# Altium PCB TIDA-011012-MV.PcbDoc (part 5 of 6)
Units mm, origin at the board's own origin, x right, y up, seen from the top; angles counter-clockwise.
Board outline 360 x 280 mm, 4 copper layers (Top Layer, Layer 1, Layer 2, Bottom Layer), stack 2.066 mm thick; 566 components, 345 nets, 1738 pads, 2486 vias.
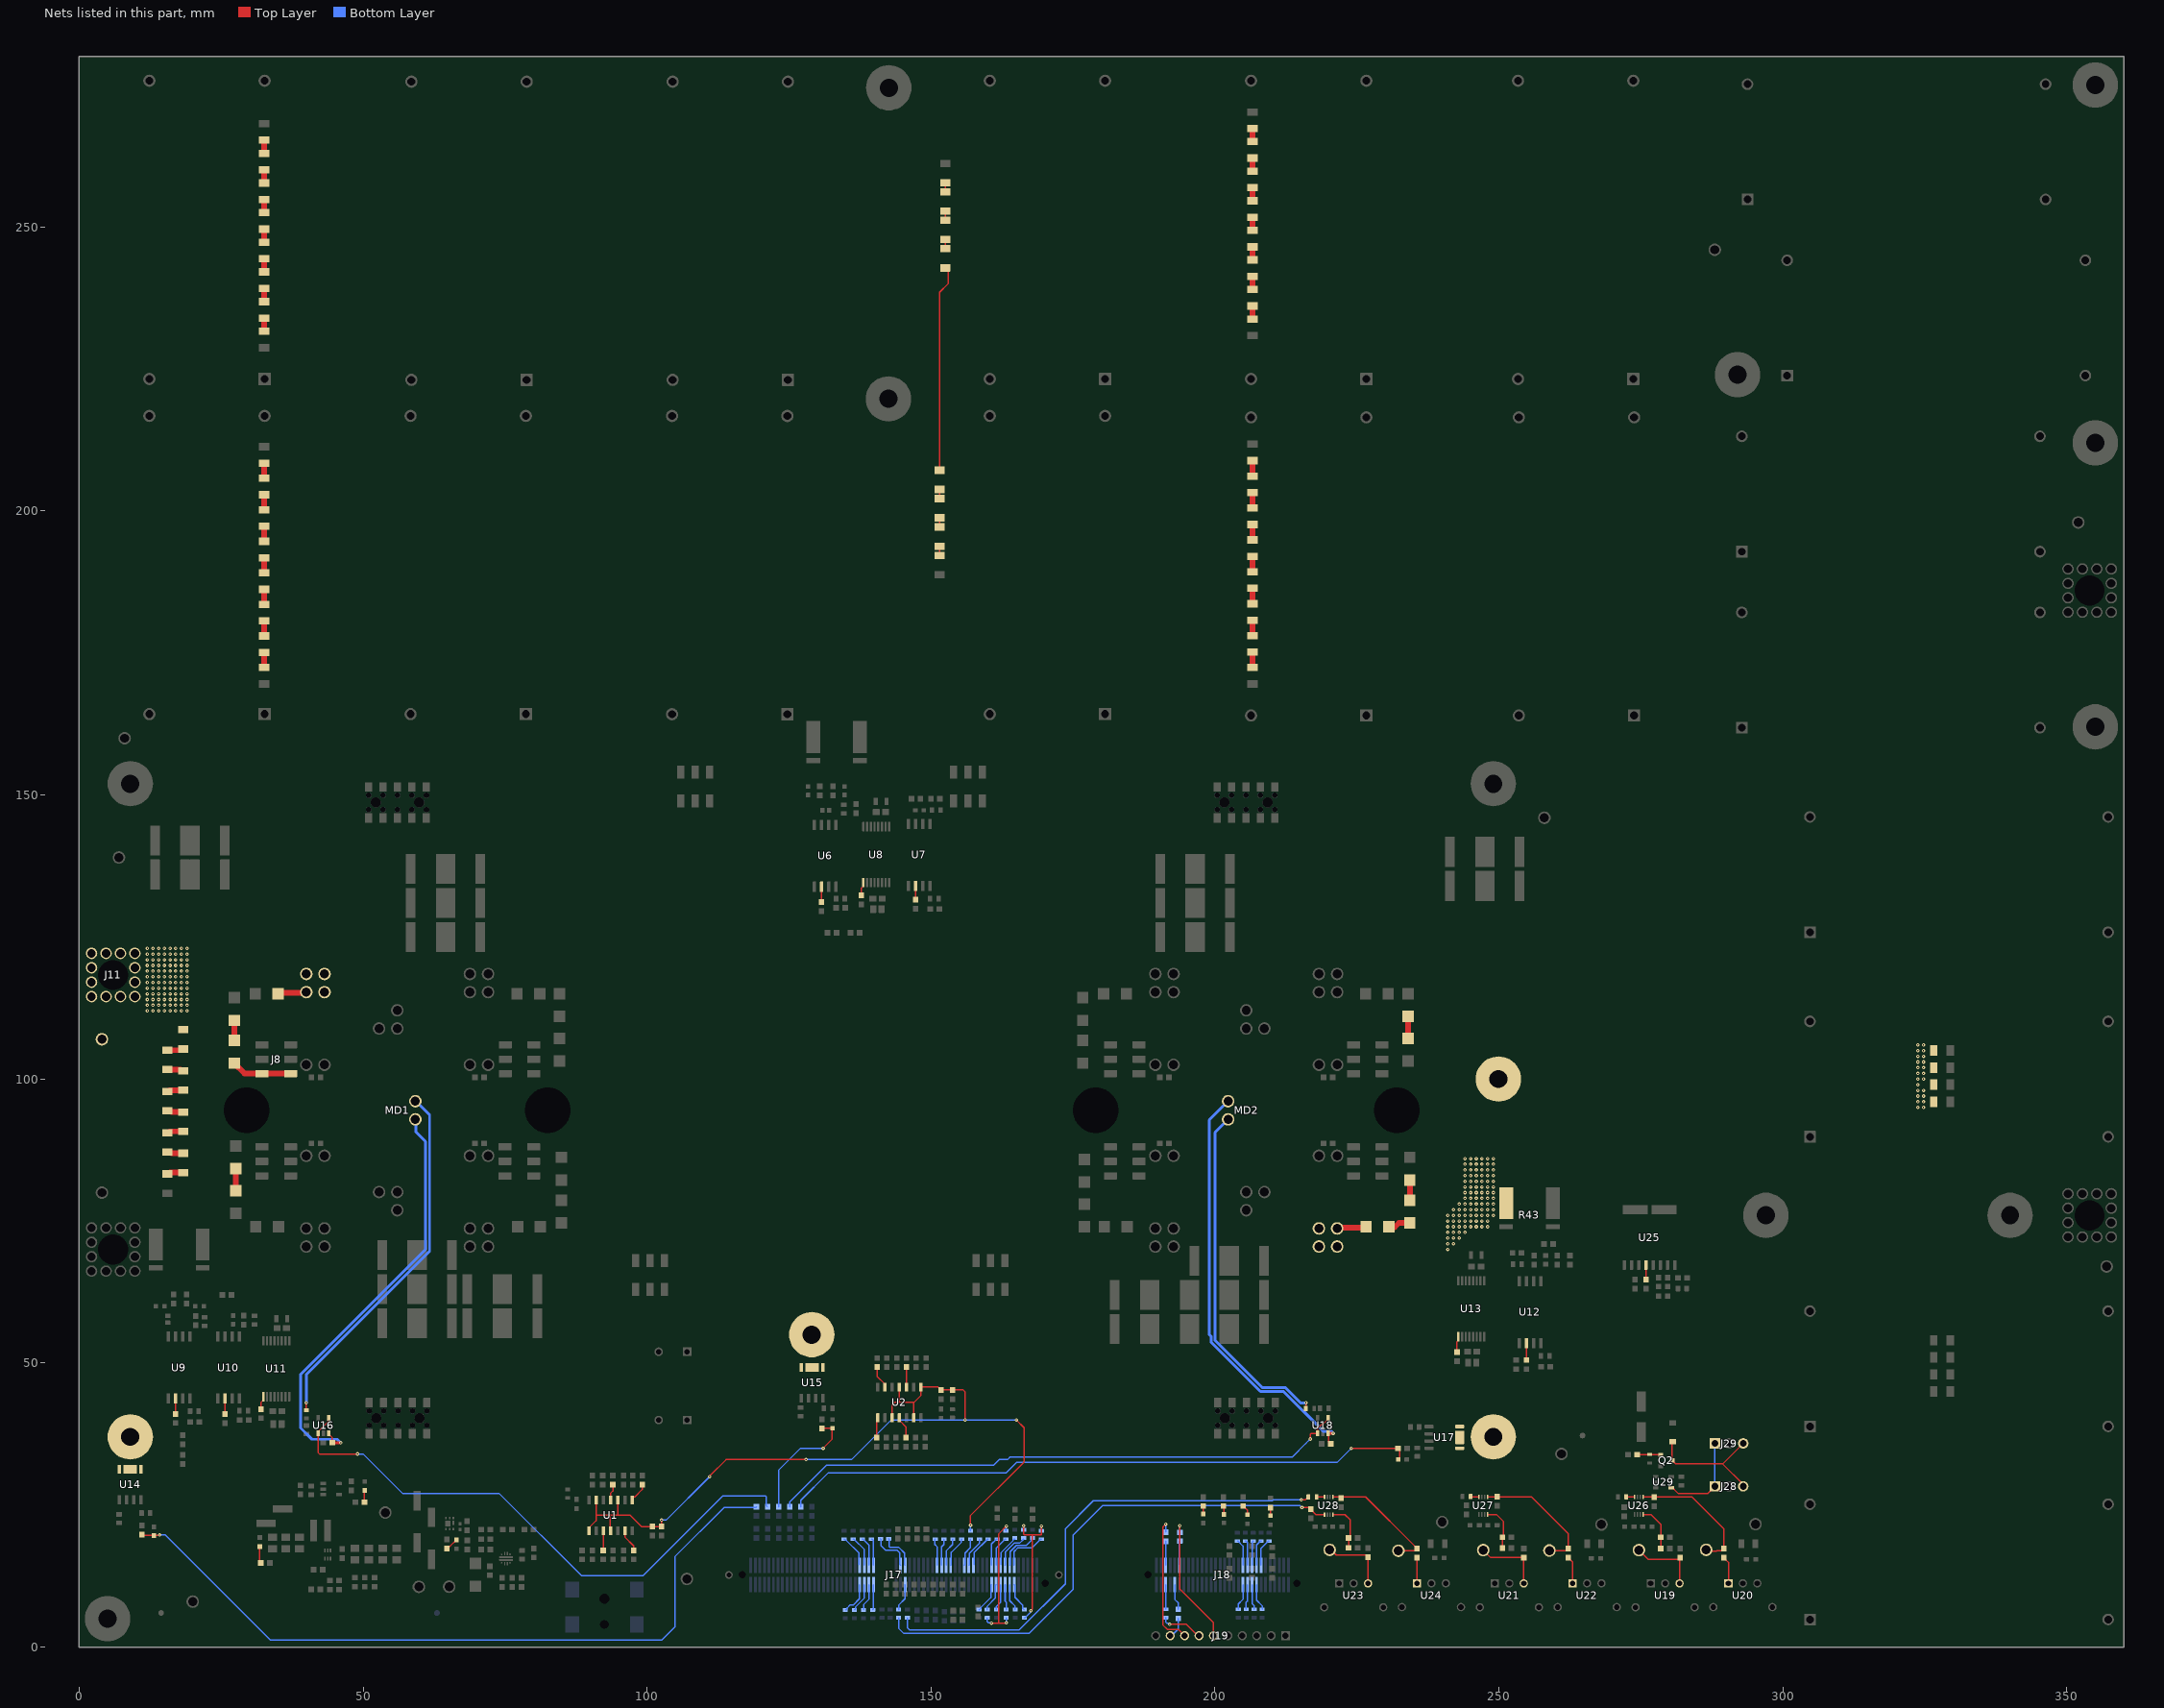
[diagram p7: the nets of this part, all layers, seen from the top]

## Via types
v1: diameter 0.6, hole 0.2, Top Layer to Bottom Layer, tented both sides, 2486 vias

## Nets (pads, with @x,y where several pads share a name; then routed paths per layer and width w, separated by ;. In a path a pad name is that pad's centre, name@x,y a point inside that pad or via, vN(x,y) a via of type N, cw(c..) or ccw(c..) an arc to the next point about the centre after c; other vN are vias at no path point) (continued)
NetD16_1: D16.1 MD2.AC2 R43.2 | length 5.1
  Top Layer w1: MD2.AC2@221.6,73.7 221.75,73.85 226.45,73.85 D16.1@226.6,74
  other v1: 241,70 241,71 242,71 241,72 242,72 243,72 241,73 242,73 243,73 244,73 241,74 242,74 243,74 244,74 245,74 246,74 247,74 248,74 241,75 242,75 243,75 244,75 245,75 246,75 247,75 248,75 241,76 242,76 243,76 244,76 245,76 246,76 247,76 248,76 249,76 242,77 243,77 244,77 245,77 246,77 247,77 248,77 249,77 243,78 244,78 245,78 246,78 247,78 248,78 249,78 244,79 245,79 246,79 247,79 248,79 249,79 244,80 245,80 246,80 247,80 248,80 249,80 244,81 245,81 246,81 247,81 248,81 249,81 244,82 245,82 246,82 247,82 248,82 249,82 244,83 245,83 246,83 247,83 248,83 249,83 244,84 245,84 246,84 247,84 248,84 249,84 244,85 245,85 246,85 247,85 248,85 249,85 244,86 245,86 246,86 247,86 248,86 249,86
NetD16_2: D16.2 D20.1 | length 3
  Top Layer w1: 231.6,73.9 232.377,74.677 D20.1@234.3,74.677
NetD17_2: D17.2 D21.1 | length 3.9
  Top Layer w1: D17.2@27.605,80.362 27.605,83.725 27.88,84 D21.1@28,84
NetD18_2: D18.2 D22.1 | length 3.5
  Top Layer w1: D22.1@27.3,106.786 D18.2@27.3,110.323
NetD19_2: D19.2 D23.1 | length 4
  Top Layer w1: D23.1@234,107.16 D19.2@234,111.023 D19.2@234,111.2
NetD20_2: D20.2 D24.1 | length 3.7
  Top Layer w1: D24.1@234.3,82.214 234.3,78.8 D20.2@234.5,78.6
NetD22_2: D22.2 J8.1 J8.2 | length 10.7
  Top Layer w1: D22.2@27.3,102.786 29.126,100.96 J8.2@37.225,100.96
NetD25_2: D25.2 R49.1 | length 1.5
  Top Layer w0.254: R49.1@201.51,24.819 201.56,24.769 D25.2@201.56,23.365
NetD26_2: D26.2 R48.1 | length 1.4
  Top Layer w0.254: D26.2@197.929,23.415 R48.1@197.929,24.819
NetD27_2: D27.2 R50.1 | length 1.4
  Top Layer w0.254: D27.2@209.753,23.146 R50.1@209.753,24.544
NetD28_2: D28.2 R52.1 | length 1.9
  Top Layer w0.254: R52.1@204.932,24.828 204.932,24.803 205.28,24.455 205.355,24.455 205.713,24.096 D28.2@205.713,23.315
NetD29_1: D29.1 R140.2 | length 2.3
  Top Layer w0.254: R140.2@64.771,17.361 64.771,17.386 65.146,17.761 65.3,17.761 D29.1@66.418,18.88
NetD31_1: D31.1 R147.2 | length 3
  Top Layer w0.254: D31.1@31.793,17.682 31.793,15.025 R147.2@32.002,14.815
NetD32_1: D32.1 R148.2 | length 2.1
  Top Layer w0.254: R148.2@50.211,25.501 50.211,27.492 D32.1@50.275,27.556
NetD33_2: D33.2 J28.3 J29.3 Q2.3 | length 23.1
  Top Layer w0.254: D33.2@280.604,36.168 280.471,36.035 Q2.3@280.471,32.855 280.521,32.855 281.137,32.24 289.39,32.24 ; J28.3@293,28.295 293,28.63 289.39,32.24 ; J29.3@293,35.85 289.39,32.24
NetH13_1: H13.1 U14.5 U14.6 U14.7
NetH14_1: H14.1 U15.5 U15.6 U15.7
NetH15_1: H15.1 U17.5 U17.6 U17.7
NetH16_1: H16.1 R211.1 R212.1 R213.1 R214.1
  other v1: 323.75,95 324.75,95 323.75,96 324.75,96 323.75,97 324.75,97 323.75,98 324.75,98 323.75,99 323.75,100 324.75,100 323.75,101 324.75,101 323.75,102 324.75,102 323.75,103 324.75,103 323.75,104 324.75,104 323.75,105 324.75,105 323.75,106 324.75,106
NetJ17_49: J17.49 R58.2 | length 5.7
  Bottom Layer w0.254: R58.2@134.703,18.994 134.901,18.796 135.081,18.796 137.324,16.554 J17.49@137.324,14.517
NetJ17_50: J17.50 R59.1 | length 5.8
  Bottom Layer w0.254: R59.1@134.89,6.545 135.015,6.545 135.213,6.743 135.213,6.868 135.757,7.412 136.312,7.412 137.4,8.5 J17.50@137.4,10.947
NetJ17_51: J17.51 R60.2 | length 5.5
  Bottom Layer w0.254: R60.2@136.303,18.994 136.428,18.994 138.247,17.175 J17.51@138.247,14.394
NetJ17_52: J17.52 R61.1 | length 5.2
  Bottom Layer w0.254: R61.1@136.503,6.545 136.527,6.545 136.725,6.743 136.725,7.1 138.247,8.623 J17.52@138.247,10.994
NetJ17_53: J17.53 R62.2 | length 5.1
  Bottom Layer w0.254: R62.2@137.903,18.994 138.028,18.994 139.047,17.975 J17.53@139.047,14.394
NetJ17_54: J17.54 R63.1 | length 4.8
  Bottom Layer w0.254: R63.1@138.116,6.545 138.116,7.466 139.047,8.397 J17.54@139.047,10.994
NetJ17_55: J17.55 R65.2 | length 4.8
  Bottom Layer w0.254: R65.2@139.503,18.994 139.628,18.994 139.847,18.775 J17.55@139.847,14.394
NetJ17_56: J17.56 R66.1 | length 4.5
  Bottom Layer w0.254: R66.1@139.728,6.545 139.847,6.664 J17.56@139.847,10.994
NetJ17_59: J17.59 R70.2 | length 7.3
  Bottom Layer w0.254: R70.2@141.077,19.044 141.178,18.943 141.178,17.848 142.02,17.007 144.071,17.007 144.524,16.554 144.524,14.517 J17.59@144.647,14.394
NetJ17_61: J17.61 R72.2 | length 6.8
  Bottom Layer w0.254: R72.2@142.521,19.044 142.622,18.943 142.622,17.674 142.771,17.526 144.352,17.526 145.324,16.554 145.324,14.517 J17.61@145.447,14.394
NetJ17_62: J17.62 R73.1 | length 4.9
  Bottom Layer w0.254: R73.1@144.286,6.594 144.286,7.376 145.4,8.489 145.4,10.947 J17.62@145.447,10.994
NetJ17_75: J17.75 R79.2 | length 4.8
  Bottom Layer w0.254: R79.2@150.722,18.994 150.672,18.944 150.672,18.05 151.047,17.675 J17.75@151.047,14.394
NetJ17_77: J17.77 R81.2 | length 4.8
  Bottom Layer w0.254: J17.77@151.847,14.394 151.847,17.625 152.28,18.058 R81.2@152.28,18.994
NetJ17_79: J17.79 R82.2 | length 5.1
  Bottom Layer w0.254: J17.79@152.647,14.394 152.647,16.919 153.778,18.05 153.778,18.933 R82.2@153.839,18.994
NetJ17_81: J17.81 R83.2 | length 5.4
  Bottom Layer w0.254: J17.81@153.447,14.394 153.57,14.517 153.57,16.674 155.333,18.437 155.333,18.93 R83.2@155.397,18.994
NetJ17_87: J17.87 R87.2 | length 5.1
  Bottom Layer w0.254: J17.87@155.847,14.394 155.97,14.517 155.97,16.554 156.955,17.539 R87.2@156.955,18.994
NetJ17_89: J17.89 R88.2 | length 5.4
  Bottom Layer w0.254: J17.89@156.647,14.394 156.77,14.517 156.77,16.554 158.514,18.297 R88.2@158.514,18.994
NetJ17_91: J17.91 R90.2 | length 5.6
  Bottom Layer w0.254: J17.91@157.57,14.517 157.57,16.617 159.947,18.994 R90.2@160.072,18.994
NetJ17_99: J17.99 R95.2 | length 5.1
  Bottom Layer w0.254: J17.99@160.647,14.394 160.647,18.136 161.505,18.994 R95.2@161.63,18.994
NetJ17_100: J17.100 R96.2 | length 5.4
  Bottom Layer w0.254: R96.2@158.422,6.594 158.547,6.594 158.745,6.792 158.745,6.917 160.524,8.696 160.524,10.871 J17.100@160.647,10.994
NetJ17_101: J17.101 R98.2 | length 5.4
  Bottom Layer w0.254: J17.101@161.447,14.394 161.447,17.378 163.063,18.994 R98.2@163.188,18.994
NetJ17_102: J17.102 R99.2 | length 5
  Bottom Layer w0.254: R99.2@159.897,6.594 159.897,7.191 161.324,8.618 161.324,10.871 J17.102@161.447,10.994
NetJ17_103: J17.103 R100.2 | length 5.5
  Bottom Layer w0.254: J17.103@162.37,14.517 162.37,16.661 164.424,18.715 164.424,18.796 164.622,18.994 R100.2@164.747,18.994
NetJ17_104: J17.104 R101.2 | length 4.7
  Bottom Layer w0.254: R101.2@161.522,6.594 161.522,7.151 162.247,7.876 J17.104@162.247,10.994
NetJ17_105: J17.105 R102.2 | length 6.5
  Bottom Layer w0.254: J17.105@163.047,14.394 163.098,14.445 163.098,16.748 164.693,18.342 165.653,18.342 R102.2@166.305,18.994
NetJ17_106: J17.106 R103.2 | length 4.5
  Bottom Layer w0.254: J17.106@163.047,10.994 163.047,8.051 163.222,7.876 R103.2@163.222,6.594
NetJ17_107: J17.107 R105.2 | length 7.3
  Bottom Layer w0.254: J17.107@163.847,14.394 163.935,14.482 163.935,16.788 165.035,17.888 166.757,17.888 167.723,18.854 R105.2@167.863,18.994
NetJ17_108: J17.108 R106.2 | length 4.8
  Bottom Layer w0.254: J17.108@163.847,10.994 163.847,8.165 164.822,7.191 R106.2@164.822,6.594
NetJ17_109: J17.109 R107.2 | length 8.2
  Bottom Layer w0.254: J17.109@164.647,14.394 164.6,14.441 164.6,16.8 165.234,17.434 167.737,17.434 169.297,18.994 R107.2@169.422,18.994
NetJ17_110: J17.110 R108.2 | length 5.2
  Bottom Layer w0.254: J17.110@164.647,10.994 164.77,10.871 164.77,8.758 166.147,7.381 166.147,6.792 166.345,6.594 R108.2@166.422,6.594
NetJ18_125: J18.125 R115.2 | length 4.2
  Bottom Layer w0.254: J18.125@191.315,14.394 R115.2@191.315,18.632
NetJ18_126: J18.126 R116.2 | length 4.4
  Bottom Layer w0.254: R116.2@191.315,6.644 J18.126@191.315,10.994
NetJ18_130: J18.130 R118.1 | length 4.6
  Bottom Layer w0.254: J18.130@192.915,10.994 192.915,8.372 193.522,7.765 R118.1@193.522,6.644
NetJ18_131: J18.131 R119.1 | length 4.3
  Bottom Layer w0.254: J18.131@193.715,14.394 193.715,18.581 R119.1@193.815,18.681
NetJ18_159: J18.159 R125.1 | length 4.7
  Bottom Layer w0.254: R125.1@203.922,18.657 204.047,18.657 204.915,17.788 J18.159@204.915,14.394
NetJ18_160: J18.160 R126.2 | length 4.7
  Bottom Layer w0.254: R126.2@204.097,6.644 204.097,7.572 204.915,8.39 J18.160@204.915,10.994
NetJ18_161: J18.161 R127.1 | length 4.5
  Bottom Layer w0.254: R127.1@205.322,18.657 205.447,18.657 205.715,18.388 J18.161@205.715,14.394
NetJ18_162: J18.162 R128.2 | length 4.4
  Bottom Layer w0.254: R128.2@205.497,6.644 205.497,7.872 205.715,8.09 J18.162@205.715,10.994
NetJ18_163: J18.163 R129.1 | length 4.4
  Bottom Layer w0.254: J18.163@206.515,14.394 206.515,18.459 206.713,18.657 R129.1@206.722,18.657
NetJ18_164: J18.164 R130.2 | length 4.5
  Bottom Layer w0.254: J18.164@206.515,10.994 206.515,8.391 206.516,8.39 206.516,7.658 206.897,7.277 R130.2@206.897,6.644
NetJ18_165: J18.165 R131.1 | length 4.7
  Bottom Layer w0.254: J18.165@207.315,14.394 207.315,17.975 207.997,18.657 R131.1@208.122,18.657
NetJ18_166: J18.166 R132.2 | length 4.8
  Bottom Layer w0.254: J18.166@207.315,10.994 207.315,8.251 208.297,7.269 R132.2@208.297,6.644
NetJ18_167: J18.167 R133.1 | length 4.9
  Bottom Layer w0.254: J18.167@208.115,14.394 208.115,17.375 209.397,18.657 R133.1@209.522,18.657
NetJ28_1: J28.1 J29.1 U29.4 | length 16.2
  Top Layer w0.254: U29.4@280.342,28.069 280.542,28.069 280.853,27.758 280.853,27.736 281.589,27 286.705,27 J28.1@288,28.295
  Bottom Layer w0.254: J28.1@288,28.295 J29.1@288,35.85
NetQ2_1: Q2.1 R187.2 R188.2 | length 4.2
  Top Layer w0.254: R187.2@274.325,33.855 274.35,33.88 R188.2@276.53,33.88 276.568,33.843 278.434,33.843 Q2.1@278.471,33.805
NetR1_1: R1.1 R5.2 | length 2.3
  Top Layer w0.5: R1.1@32.54,265.05 R1.1@32.54,265.3
  Top Layer w1: R5.2@32.54,262.979 R1.1@32.54,265.05
NetR2_1: R2.1 R13.1 | length 2.3
  Top Layer w1: R2.1@32.54,247.314 R13.1@32.54,249.636
NetR2_2: R2.2 R6.1 | length 2.3
  Top Layer w1: R6.1@32.54,242.093 R2.2@32.54,244.414
NetR3_1: R3.1 R7.2 | length 2.3
  Top Layer w0.5: R3.1@206.592,267.1 R3.1@206.592,267.35
  Top Layer w1: R7.2@206.592,265.043 R3.1@206.592,267.1
NetR4_1: R4.1 R15.1 | length 2.3
  Top Layer w1: R4.1@206.592,249.421 R15.1@206.592,251.729
NetR4_2: R4.2 R8.1 | length 2.3
  Top Layer w1: R8.1@206.592,244.214 R4.2@206.592,246.521
NetR5_1: R5.1 R9.2 | length 2.3
  Top Layer w1: R9.2@32.54,257.757 R5.1@32.54,260.079
NetR6_2: R6.2 R10.1 | length 2.3
  Top Layer w1: R10.1@32.54,236.871 R6.2@32.54,239.193
NetR7_1: R7.1 R11.2 | length 2.3
  Top Layer w1: R11.2@206.592,259.836 R7.1@206.592,262.143
NetR8_2: R8.2 R12.1 | length 2.3
  Top Layer w1: R12.1@206.592,239.007 R8.2@206.592,241.314
NetR9_1: R9.1 R13.2 | length 2.3
  Top Layer w1: R13.2@32.54,252.536 R9.1@32.54,254.857
NetR10_2: R10.2 R14.1 | length 2.3
  Top Layer w1: R14.1@32.54,231.65 R10.2@32.54,233.971
NetR11_1: R11.1 R15.2 | length 2.3
  Top Layer w1: R15.2@206.592,254.629 R11.1@206.592,256.936
NetR12_2: R12.2 R16.1 | length 2.3
  Top Layer w1: R16.1@206.592,233.8 R12.2@206.592,236.107
NetR21_2: R21.2 R25.1 | length 2.7
  Top Layer w1: R25.1@32.54,205.767 R21.2@32.54,208.42
NetR22_2: R22.2 R28.1 | length 2.7
  Top Layer w1: R28.1@206.592,206.153 R22.2@206.592,208.87
NetR23_1: R23.1 R31.2 | length 2.7
  Top Layer w1: R31.2@32.54,183.556 R23.1@32.54,186.209
NetR23_2: R23.2 R37.2 | length 2.7
  Top Layer w1: R23.2@32.54,189.109 R37.2@32.54,191.761
NetR24_1: R24.1 R32.2 | length 2.7
  Top Layer w1: R32.2@206.592,183.684 R24.1@206.592,186.401
NetR24_2: R24.2 R38.2 | length 2.7
  Top Layer w1: R24.2@206.592,189.301 R38.2@206.592,192.019
NetR25_2: R25.2 R33.1 | length 2.7
  Top Layer w1: R33.1@32.54,200.214 R25.2@32.54,202.867
NetR28_2: R28.2 R34.1 | length 2.7
  Top Layer w1: R34.1@206.592,200.536 R28.2@206.592,203.253
NetR31_1: R31.1 R35.2 | length 2.7
  Top Layer w1: R35.2@32.54,178.003 R31.1@32.54,180.656
NetR32_1: R32.1 R36.2 | length 2.7
  Top Layer w1: R36.2@206.592,178.067 R32.1@206.592,180.784
NetR33_2: R33.2 R37.1 | length 2.7
  Top Layer w1: R37.1@32.54,194.661 R33.2@32.54,197.314
NetR34_2: R34.2 R38.1 | length 2.7
  Top Layer w1: R38.1@206.592,194.919 R34.2@206.592,197.636
NetR35_1: R35.1 R39.2 | length 2.7
  Top Layer w0.5: R39.2@32.54,172.45 R39.2@32.54,172.7
  Top Layer w1: R39.2@32.54,172.7 R35.1@32.54,175.103
NetR36_1: R36.1 R40.2 | length 2.7
  Top Layer w0.5: R40.2@206.592,172.45 R40.2@206.592,172.7
  Top Layer w1: R40.2@206.592,172.7 R36.1@206.592,175.167
NetR75_1: R75.1 U1.3 | length 3.5
  Top Layer w0.254: R75.1@92.276,17.034 U1.3@92.276,20.484
NetR76_1: R76.1 U1.6 | length 4.1
  Top Layer w0.254: U1.6@96.086,20.484 96.086,19.363 97.63,17.82 R76.1@97.63,17.034
NetR80_1: R80.1 U1.8 | length 3.6
  Top Layer w0.254: U1.8@97.356,25.884 97.356,26.299 97.529,26.472 97.883,26.472 99.141,27.73 R80.1@99.141,28.584
NetR84_1: R84.1 U1.11 | length 2.9
  Top Layer w0.254: U1.11@93.546,25.884 93.546,27.056 93.964,27.474 R84.1@93.964,28.584
NetR111_1: R111.1 U2.3 | length 3.5
  Top Layer w0.254: R111.1@145.67,49.275 145.702,49.243 U2.3@145.702,45.775
NetR112_1: R112.1 U2.6 | length 4.1
  Top Layer w0.254: R112.1@140.516,49.275 140.516,47.625 141.892,46.25 U2.6@141.892,45.775
NetR114_1: R114.1 U2.8 | length 3.6
  Top Layer w0.254: R114.1@140.399,36.875 140.399,39.677 140.622,39.9 U2.8@140.622,40.375
NetR117_1: R117.1 U2.11 | length 4
  Top Layer w0.254: U2.11@144.432,40.375 144.432,39.9 145.553,38.779 R117.1@145.553,36.875
NetR153_1: R153.1 U6.6 | length 2.7
  Top Layer w0.254: R153.1@130.731,131.191 U6.6@130.731,133.863
NetR155_2: R155.2 R156.1 | length 1.6
  Top Layer w0.254: R156.1@152.5,256.2 R155.2@152.5,257.8
NetR156_2: R156.2 R157.1 | length 1.6
  Top Layer w0.254: R157.1@152.5,251.2 R156.2@152.5,252.8
NetR157_2: R157.2 R158.1 | length 1.6
  Top Layer w0.254: R158.1@152.5,246.2 R157.2@152.5,247.8
NetR158_2: R158.2 R159.1 | length 36.4
  Top Layer w0.254: R159.1@151.5,207.2 151.5,238.5 153,240 R158.2@153,243
NetR159_2: R159.2 R160.1 | length 1.6
  Top Layer w0.254: R160.1@151.5,202.2 R159.2@151.5,203.8
NetR160_2: R160.2 R161.1 | length 1.6
  Top Layer w0.254: R161.1@151.5,197.2 R160.2@151.5,198.8
NetR161_2: R161.2 R162.1 | length 1.6
  Top Layer w0.254: R162.1@151.5,192.2 R161.2@151.5,193.8
NetR163_1: R163.1 U7.6 | length 2.4
  Top Layer w0.254: R163.1@147.266,131.607 U7.6@147.266,134.013
NetR165_1: R165.1 U8.1 | length 2.4
  Top Layer w0.254: R165.1@137.728,132.328 137.728,133.605 138.091,133.968 U8.1@138.091,134.588
NetR168_1: R168.1 U9.6 | length 2.7
  Top Layer w0.254: R168.1@16.965,41.05 U9.6@16.965,43.75
NetR170_2: R170.2 R171.1 | length 2.9
  Top Layer w1: R171.1@15.5,105.071 17.84,105.071 18.069,105.3 R170.2@18.319,105.3
NetR171_2: R171.2 R172.1 | length 2.9
  Top Layer w1: R171.2@15.5,101.671 17.84,101.671 18.069,101.443 R172.1@18.319,101.443
NetR172_2: R172.2 R173.1 | length 2.9
  Top Layer w1: R173.1@15.5,97.814 15.75,97.814 15.979,98.043 R172.2@18.319,98.043
NetR173_2: R173.2 R174.1 | length 2.9
  Top Layer w1: R173.2@15.5,94.414 15.65,94.264 16.2,94.264 16.279,94.186 R174.1@18.319,94.186
NetR174_2: R174.2 R175.1 | length 2.9
  Top Layer w1: R175.1@15.5,90.557 15.75,90.557 15.979,90.786 R174.2@18.319,90.786
NetR175_2: R175.2 R176.1 | length 2.9
  Top Layer w1: R175.2@15.5,87.157 15.65,87.007 16.2,87.007 16.279,86.929 R176.1@18.319,86.929
NetR176_2: R176.2 R177.1 | length 2.9
  Top Layer w1: R177.1@15.5,83.3 15.75,83.3 15.979,83.529 R176.2@18.319,83.529
NetR178_1: R178.1 U10.6 | length 2.7
  Top Layer w0.254: R178.1@25.665,41.021 U10.6@25.665,43.75
NetR180_1: R180.1 U11.1 | length 2.4
  Top Layer w0.254: R180.1@32,41.896 32,43.03 32.425,43.455 U11.1@32.425,44.075
NetR183_1: R183.1 U12.6 | length 3
  Top Layer w0.254: R183.1@254.83,50.528 U12.6@254.83,53.5
NetR185_1: R185.1 U13.1 | length 2.8
  Top Layer w0.254: R185.1@242.615,51.953 242.615,53.787 242.84,54.012 U13.1@242.84,54.632
NetR194_2: R194.2 TP4.1 U19.3 | length 12.3
  Top Layer w0.254: TP4.1@274.649,17.075 276.249,15.475 281.917,15.475 281.788,15.346 U19.3@281.788,11.201
NetR195_1: R195.1 U20.1 | length 4.8
  Top Layer w0.254: R195.1@289.606,15.725 289.606,15.7 290.399,14.907 U20.1@290.399,11.226
NetR197_2: R197.2 TP7.1 U21.3 | length 12.2
  Top Layer w0.254: TP7.1@247.231,17.075 248.555,15.75 R197.2@254.369,15.75 U21.3@254.369,11.201
NetR198_1: R198.1 U22.1 | length 4.9
  Top Layer w0.254: R198.1@262.187,15.75 262.187,15.725 262.98,14.932 U22.1@262.98,11.226
NetR199_1: R199.1 U25.6 | length 2.5
  Top Layer w0.254: R199.1@275.865,64.725 U25.6@275.865,67.247
NetR209_2: R209.2 TP10.1 U23.3 | length 11.9
  Top Layer w0.254: TP10.1@220.19,17.112 220.443,17.112 221.346,16.209 226.576,16.209 226.951,15.834 R209.2@226.951,15.809 U23.3@226.951,11.201
NetR210_1: R210.1 U24.1 | length 4.5
  Top Layer w0.254: U24.1@235.561,11.226 R210.1@235.561,15.753
NetR215_2: R215.2 U26.4 | length 1.5
  Top Layer w0.254: R215.2@272.406,26.445 U26.4@273.881,26.445
NetR216_2: R216.2 U27.4 | length 1.5
  Top Layer w0.254: R216.2@245.005,26.495 245.055,26.445 U27.4@246.481,26.445
NetR217_2: R217.2 U28.4 | length 1.4
  Top Layer w0.254: R217.2@217.877,26.419 U28.4@219.269,26.419
NTC1_N: MD1.T2 R190.2 U16.3 | length 75.7
  Top Layer w0.254: U16.3@43.95,37.625 43.95,37.425 44.123,37.252 44.158,37.252 44.554,36.856 R190.2@44.554,36
  Top Layer w0.5: R190.2@44.554,36 44.601,35.953 v1(46.045,35.953)
  Bottom Layer w0.5: v1(46.045,35.953) 45.416,36.583 40.963,36.583 39,38.545 39,48 61,70 61,89 59.3,90.7 MD1.T2@59.3,92.9
NTC1_P: MD1.T1 R218.1 | length 64.4
  Top Layer w0.254: R218.1@40,41.725 v1(40,43)
  Bottom Layer w0.5: v1(40,43) 40,48 61.7,69.7 61.7,93.7 MD1.T1@59.3,96.1
NTC2_N: MD2.T2 R192.2 U18.3 | length 74.9
  Top Layer w0.254: U18.3@219.95,37.625 219.986,37.589 219.986,36.125 R192.2@220.334,35.777
  Top Layer w0.5: U18.3@219.95,37.625 v1(220.8,37.625)
  Bottom Layer w0.5: MD2.T2@202.3,96.1 199,92.8 199,55 199.3,54.7 199.3,53.7 208,45 212.061,45 219.061,38 220.425,38 v1(220.8,37.625)
NTC2_P: MD2.T1 R219.1 | length 61.4
  Top Layer w0.254: R219.1@216,42 v1(216,43)
  Bottom Layer w0.5: MD2.T1@202.3,92.9 200,90.6 200,53.99 208.29,45.7 212.351,45.7 215.051,43 v1(216,43)
PWM_BUF_EN: C42.2 C53.2 R87.1 R204.2 R205.2 U1.1 U1.4 U1.10 U1.13 U2.1 U2.4 U2.10 U2.13 | length 145.6
  Top Layer w0.254: U1.1@89.736,20.484 89.736,20.959 91.006,22.229 91.006,23.184 ; U1.13@91.006,25.409 91.006,23.184 ; U1.4@93.532,20.498 93.532,23.184 ; 93.939,23.184 93.532,23.184 ; 93.952,23.184 94.816,23.184 ; U1.10@94.816,25.409 94.816,23.184 ; v1(102.546,22.346) R204.2@102.546,21.232 C42.2@100.962,21.232 98.994,21.232 97.041,23.184 94.816,23.184 ; v1(111,30) 111,30.067 111.123,30.19 111.123,30.229 113.894,33 v1(128,33) ; U2.10@143.162,40.375 143.162,42.654 143.57,43.062 144.453,43.062 ; U2.4@144.432,45.775 144.432,43.083 144.453,43.062 ; U2.13@146.972,40.375 146.972,43.062 ; v1(156,40) 156,44.933 155.673,45.26 153.765,45.26 R205.2@153.763,45.258 C53.2@151.773,45.258 151.773,45.283 151.425,45.631 151.4,45.631 151.256,45.775 U2.1@148.242,45.775 148.242,44.332 146.972,43.062 ; v1(156.955,21.468) 156.955,23.156 166.375,32.576 166.375,38.625 v1(165,40) ; 91.006,23.184 93.532,23.184 ; 144.453,43.062 146.972,43.062
  Bottom Layer w0.254: v1(102.546,22.346) 103.346,22.346 v1(111,30) ; v1(128,33) 136,33 143,40 v1(156,40) v1(165,40) ; R87.1@156.955,20.444 v1(156.955,21.468)
PWM_CLK_SD_AC_DELAYED: R98.1 R99.1 R103.1 | length 23.6
  Top Layer w0.254: v1(160.647,4.219) 161.93,4.219 ; v1(163.272,4.277) 163.213,4.219 161.93,4.219 ; v1(163.272,21.294) 161.93,19.952 161.93,4.219
  Bottom Layer w0.254: R99.1@159.897,5.144 159.897,4.438 160.069,4.266 160.6,4.266 v1(160.647,4.219) ; R98.1@163.188,20.444 163.188,21.144 163.272,21.228 v1(163.272,21.294) ; R103.1@163.222,5.144 163.272,5.094 v1(163.272,4.277)
PWM_CLK_SD_DC_DELAYED: R102.1 R107.1 R108.1 | length 23.3
  Top Layer w0.254: v1(166.305,21.367) 166.305,19.868 166.454,19.719 167.863,19.719 ; v1(167.578,6.394) 167.863,6.68 167.863,19.719 ; v1(169.436,21.294) 169.436,19.719 167.863,19.719
  Bottom Layer w0.254: R102.1@166.305,20.444 v1(166.305,21.367) ; R108.1@166.422,5.144 166.547,5.144 167.531,6.128 167.531,6.347 v1(167.578,6.394) ; R107.1@169.422,20.444 169.436,20.458 v1(169.436,21.294)
PWM_SYNC_RX: R74.2 R217.1 | length 88
  Top Layer w0.254: v1(215.204,25.894) 215.902,25.894 216.104,26.096 216.229,26.096 216.427,26.294 R217.1@216.427,26.419
  Bottom Layer w0.254: R74.2@145.836,5.144 145.836,3.376 146.212,3 165.515,3 173.651,11.136 173.651,20.828 178.574,25.75 210.06,25.75 210.204,25.894 v1(215.204,25.894)
PWM_SYNC_TX: C151.1 R73.2 U28.5 | length 92.7
  Top Layer w0.254: v1(215.304,24.544) 216.57,24.544 C151.1@216.849,24.265 ; C151.1@216.849,24.24 217.77,23.319 U28.5@219.269,23.319
  Bottom Layer w0.254: R73.2@144.286,5.144 144.286,3.312 145.141,2.457 167.323,2.457 175,10.134 175,19.699 180.17,24.869 214.979,24.869 v1(215.304,24.544)
RXCLK_5V: C148.1 R195.2 TP6.1 U26.1 | length 23.4
  Top Layer w0.254: U26.1@275.381,26.445 283.967,26.445 289.606,20.807 289.606,17.3 289.231,16.925 288.34,16.925 288.311,16.896 286.708,16.896 TP6.1@286.492,17.112
RXD0_5V: C150.1 R198.2 TP9.1 U27.1 | length 23
  Top Layer w0.254: U27.1@247.981,26.445 255.716,26.445 262.187,19.975 R198.2@262.187,17.35 261.836,17 TP9.1@258.87,17
RXD1_5V: C152.1 R210.2 TP12.1 U28.1 | length 22
  Top Layer w0.254: U28.1@220.769,26.419 226.495,26.419 235.161,17.753 235.186,17.753 235.561,17.378 R210.2@235.561,17.353 235.561,17.328 235.186,16.953 232.303,16.953 TP12.1@232.3,16.95
SPIB_CLK: J19.9 R118.2 | length 3.8
  Bottom Layer w0.254: J19.9@192.11,2 192.343,2 193.522,3.179 R118.2@193.522,5.044
SPIB_PICO: J19.8 R115.1 | length 24
  Top Layer w0.254: v1(191.315,21.63) 190.788,21.103 190.788,3.913 191.574,3.127 193.523,3.127 J19.8@194.65,2
  Bottom Layer w0.254: R115.1@191.315,20.232 v1(191.315,21.63)
SPIB_POCI: J19.7 R116.1 | length 7.7
  Top Layer w0.254: v1(192,4) 194.961,4 196.961,2 J19.7@197.19,2
  Bottom Layer w0.254: R116.1@191.315,5.194 191.315,4.387 191.475,4.227 191.707,4.227 191.933,4 v1(192,4)
SPIB_PTE: J19.6 R119.2 | length 23
  Top Layer w0.254: v1(193.815,21.362) 193.815,10.185 199.73,4.27 J19.6@199.73,2
  Bottom Layer w0.254: R119.2@193.815,20.182 v1(193.815,21.362)
TEMP1: C124.2 R44.1 R186.1 | length 132.9
  Top Layer w0.254: R186.1@11.016,19.79 11.166,19.64 C124.2@13.166,19.64 14.066,19.64 v1(14.141,19.715)
  Bottom Layer w0.254: v1(14.141,19.715) 15.187,19.715 33.659,1.243 102.579,1.243 104.951,3.615 104.951,15.978 113.562,24.589 119.169,24.589 R44.1@119.25,24.67
TEMP2: C127.2 R56.1 R189.1 | length 22
  Top Layer w0.254: R189.1@130.81,38.51 130.846,38.545 C127.2@132.614,38.545 132.604,38.535 132.604,36.604 v1(131,35)
  Bottom Layer w0.254: R56.1@123.15,24.67 123.15,31.15 127,35 v1(131,35)
TEMP3: C131.2 R77.1 R191.1 | length 112.5
  Top Layer w0.254: v1(224,35) 231.957,35 232.078,35.122 232.505,34.695 232.505,33.248 232.257,33 C131.2@232.25,33
  Bottom Layer w0.254: R77.1@127.05,24.67 127.05,25.843 131.847,30.64 131.847,30.674 163.24,30.674 165.112,32.546 221.546,32.546 v1(224,35)
TEMP4: R51.1 U16.1 U16.4 | length 102.5
  Top Layer w0.254: U16.4@43.95,40.375 43.833,40.258 43.833,39.691 43.02,38.878 42.223,38.081 42.223,37.798 U16.1@42.05,37.625 42.05,34.256 42.306,34 v1(49,34)
  Bottom Layer w0.254: v1(49,34) 50,34 57,27 74,27 88.416,12.584 99.322,12.584 113.363,26.625 120.851,26.625 121,26.476 121,24.87 R51.1@121.159,24.711
TEMP5: R67.1 U18.1 U18.4 | length 103
  Top Layer w0.254: v1(216.781,36.625) 216.781,37.476 216.93,37.625 U18.1@218.05,37.625 218.05,38.475 218.814,39.238 219.014,39.238 219.95,40.175 U18.4@219.95,40.375
  Bottom Layer w0.254: R67.1@125.1,24.67 125.1,25.501 131.599,32 161,32 162,33 163.463,33 163.917,33.454 213.61,33.454 216,35.844 v1(216.781,36.625)
TXCLK_5V: C134.2 R193.1 U26.8 | length 8.1
  Top Layer w0.254: U26.8@275.381,23.345 276.732,23.345 278.5,21.578 R193.1@278.5,19.35 C134.2@278.5,17.35
TXD0_5V: C136.2 R196.1 U27.8 | length 8.1
  Top Layer w0.254: U27.8@247.981,23.345 249.555,23.345 250.8,22.1 250.8,19.521 R196.1@250.604,19.325 C136.2@250.604,17.425
TXD1_5V: C139.2 R208.1 U28.8 | length 8.5
  Top Layer w0.254: U28.8@220.769,23.319 222.892,23.319 223.8,22.411 223.8,19.485 C139.2@223.528,19.212 R208.1@223.528,17.463
VAC_POS: D14.1 J11.1 MD1.AC2 R170.1 TP19.1 | length 5.2
  Top Layer w1: D14.1@35,115 35.15,115.15 39.95,115.15 MD1.AC2@40.1,115.3
  other v1: 12,112 13,112 14,112 15,112 16,112 17,112 18,112 19,112 12,113 13,113 14,113 15,113 16,113 17,113 18,113 19,113 12,114 13,114 14,114 15,114 16,114 17,114 18,114 19,114 12,115 13,115 14,115 15,115 16,115 17,115 18,115 19,115 12,116 13,116 14,116 15,116 16,116 17,116 18,116 19,116 12,117 13,117 14,117 15,117 16,117 17,117 18,117 19,117 12,118 13,118 14,118 15,118 16,118 17,118 18,118 19,118 12,119 13,119 14,119 15,119 16,119 17,119 18,119 19,119 12,120 13,120 14,120 15,120 16,120 17,120 18,120 19,120 12,121 13,121 14,121 15,121 16,121 17,121 18,121 19,121 12,122 13,122 14,122 15,122 16,122 17,122 18,122 19,122 12,123 13,123 14,123 15,123 16,123 17,123 18,123 19,123
pads on no net: FID1.1 FID2.1 FID3.1 H1.1 H2.1 H3.1 H4.1 H5.1 H6.1 H7.1 H8.1 H9.1 H10.1 H12.1 J5. J6. J11. J12. J13. J14. J15. J16. J17.1 J17.2 J17.3 J17.4 J17.5 J17.6 J17.8 J17.12 J17.14 J17.18 J17.20 J17.23 J17.24 J17.26 J17.27 J17.28 J17.29 J17.30 J17.31 J17.32 J17.33 J17.34 J17.36 J17.37 J17.39 J17.40 J17.41 J17.42 J17.43 J17.44 J17.45 J17.57 J17.63 J17.66 J17.80 J17.82 J17.85 J17.86 J17.88 J17.90 J17.92 J17.93 J17.94 J17.95 J17.96 J17.113 J17.114 J17.115 J17.116 J17.117 J17.118 J17.119 J17.120 J17.181 J17.182 J17.185 J17.186 J18.61 J18.62 J18.121 J18.122 J18.123 J18.124 J18.127 J18.128 J18.129 J18.132 J18.133 J18.134 J18.136 J18.137 J18.138 J18.139 J18.140 J18.141 J18.142 J18.143 J18.144 J18.145 J18.146 J18.147 J18.148 J18.149 J18.150 J18.151 J18.152 J18.153 J18.154 J18.155 J18.156 J18.168 J18.169 J18.170 J18.171 J18.172 J18.173 J18.174 J18.175 J18.176 J18.177 J18.178 J21.MH1 J21.MH2 LBL1.0 MD1. MD2. Q1.0 U14.2 U15.2 U17.2 U19.1 U19.4 U19.5 U20.4 U20.5 U21.1 U21.4 U21.5 U22.4 U22.5 U23.1 U23.4 U23.5 U24.4 U24.5 U25.4 U25.5 U29.1

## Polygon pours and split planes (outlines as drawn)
GND on Layer 1 "LAYER_1_GND_P173" (solid, remove dead copper, pour order 173): 0,11 8,11 11,8 11,0 297,0 297,66 272,66 261,55 234.25,55 223.01,43.76 175.24,43.76 153,66 153,119 176,142 209,142 213,146 213,153 209,157 170,157 163,150 148,135 115,135 92,158 56,158 50,152 50,146 53,143 86.5,143 107,122.5 107,60 91,44 0,44 0,22
DC_BUS_DAB on Layer 1 "LAYER_1_DC_BUS_DAB_P276" (solid, remove dead copper, pour order 276): 211.5,113.1 215.5,109.1 215.5,82.1 209.5,76.1 203.5,76.1 203.5,89.1 206.5,92.1 206.5,98.1 203.5,101.1 203.5,113.1
DC_BUS_NEG on Layer 1 "LAYER_1_DC_BUS_NEG_P275" (solid, remove dead copper, pour order 275): 50,76 46,80 46,107 52,113 58,113 58,100 55,97 55,91 58,88 58,76
GND_ISO_AC_SENS on Layer 1 "LAYER_1_GND_ISO_AC_SENS_P274" (solid, remove dead copper, pour order 274): 1,62 1,78 11,78 11,64 9,62
I_HALL_N on Layer 1 "LAYER_1_I_HALL_N_P271" (solid, remove dead copper, pour order 271): 258,87 276,87 276,76 258,76
GND_ISO_AC_SENS on Layer 1 "LAYER_1_GND_ISO_AC_SENS_P232" (solid, remove dead copper, pour order 232): 11,61 11,53 38,53 38,63 13,63
DC_BUS_POS on Layer 1 "Layer 1-DC_BUS_POS" (solid, remove dead copper, pour order 175): 244,146 252,146 255,149 260,149 260,143 250,143 242,135 234,127 206,127 200,121 200,113 196,109 185,109 173,97 173,91 184,80 197,80 210,67 216,67 216,50 176,50 157,69 157,120 178,141 208,141 211,144 211,171 55,171 51.081,167.081 51.059,160.059 47,156 47,145 51,141 85,141 105,121 105,61 94,50 58,50 50,58 50,70 59,70 63,74 63,81 80,81 89,90 89,99 79,109 63,109 63,115 57,121 55,121 55.05,121.05 47.1,129 23,129 16,136 16,162.007 2,175.974 2,278 131,278 131,266 153,266 153,278 284,278 284,159 244,159 242,157 242,148
I_HALL_P on Layer 1 "LAYER_1_I_HALL_P_P222" (solid, remove dead copper, pour order 222): 302,67 305,70 305,79 301,83 293,83 286,76 277,76 277,92 301,116 301,148 303,150 314,150 316,148 316,0 302,0
DC_BUS_DAB on Layer 1 "LAYER_1_DC_BUS_DAB_P252" (solid, remove dead copper, pour order 252): 127,144 127,157 140,157 140,151 153,151 153,144
I_SW_NEG on Layer 1 "LAYER_1_I_SW_NEG_P249" (solid, remove dead copper, pour order 249): 242,63 260,63 263,66 263,72 247,72 242,67
VAC_POS on Layer 1 "LAYER_1_VAC_POS_P243" (solid, remove dead copper, pour order 243): 1,110 17.5,110 42,110 46,114 46,120 42,124 1,124
NetD13_1 on Layer 1 "LAYER_1_NETD13_1_P242" (solid, remove dead copper, pour order 242): 21,74 21,68 24,68 24,65 25,64 40,64 45,69 45,75 38,75 38,70 27,70 25,72 23,74
no net on Layer 1 "LAYER_1_NONET_P233" (solid, remove dead copper, pour order 233): 1,78 15,78 15,68 11,68 11,64 1,64
NetD16_1 on Layer 1 "LAYER_1_NETD16_1_P228" (solid, remove dead copper, pour order 228): 243,82 243,87 253,87 253,73 245,73 239,67 216,67 216,74 218,76 237,76
NetC177_1 on Layer 1 "LAYER_1_NETC177_1_P213" (solid, remove dead copper, pour order 213): 259,130 264,135 264,143 264,149 268,153 286,153 288,155 288,213 298,223 298,226 290,234 290,278 308,278 308,224 308,156 261,109 221,109 215,115 215,119 218,122 237,122 245,130
NetC173_2 on Layer 1 "LAYER_1_NETC173_2_P225" (solid, remove dead copper, pour order 225): 348,150 348,0 360,0 360,150
NetC177_2 on Layer 1 "LAYER_1_NETC177_2_P217" (solid, remove dead copper, pour order 217): 340,277 351,277 351,252 357,246 357,221 356,221 348,213 348,205 360,193 360,179 349,168 349,158 340,158
AC_KS2 on Layer 1 "LAYER_1_AC_KS2_P197" (solid, remove dead copper, pour order 197): 31,90 31,86 31,82 44,82 44,90
AC_KS4 on Layer 1 "LAYER_1_AC_KS4_P196" (solid, remove dead copper, pour order 196): 45,99 45,104 31,104 31,99
GND on Layer 2 "LAYER_2_GND_P277" (solid, remove dead copper, pour order 277): 1,11 7,11 11,7 11,1 297,1 297,66 272,66 261,55 234,55 223,44 175,44 150,69 118,69 93,44 1,44
NetD16_1 on Layer 2 "LAYER_2_NETD16_1_P281" (solid, remove dead copper, pour order 281): 243,82 243,87 253,87 253,73 245,73 239,67 216,67 216,74 218,76 237,76
I_HALL_N on Layer 2 "LAYER_2_I_HALL_N_P273" (solid, remove dead copper, pour order 273): 258,87 276,87 276,76 258,76
GND_ISO_AC_SENS on Layer 2 "LAYER_2_GND_ISO_AC_SENS_P238" (solid, remove dead copper, pour order 238): 11,53 11,61 13,63 16,63 16,77 18,77 18,67 22,63 38,63 38,53
DC_BUS_DAB on Layer 2 "Layer 2-DC_BUS_DAB" (solid, remove dead copper, pour order 212): 285,243 291,243 291,249 285,249 285,278 150,278 150,211 137,198 137,161 143,161 157,147 157,65 172,50 216,50 216,129 218,131 231,131 242,142 242,160 285,160
DC_BUS_NEG on Layer 2 "Layer 2-DC_BUS_NEG" (solid, remove dead copper, pour order 176): 46,80 50,76 50,58 58,50 93,50 98,55 113,70 113,151.003 123.392,161.36 131.008,161.333 131,161.341 131,260 112,279 2,279 2,162.035 15,161.99 15,137 23,129 44,129 51,122 51,112 46,107
VAC_POS on Layer 2 "LAYER_2_VAC_POS_P174" (solid, remove dead copper, pour order 174): 1,110 17.5,110 42,110 45,113 45,121 42,124 1,124
NetD13_1 on Layer 2 "LAYER_2_NETD13_1_P239" (solid, remove dead copper, pour order 239): 21,74 21,68 24,68 24,65 25,64 40,64 45,69 45,75 38,75 38,70 27,70 25,72 23,74
GND_ISO_AC_SENS on Layer 2 "LAYER_2_GND_ISO_AC_SENS_P236" (solid, remove dead copper, pour order 236): 1,78 13,78 15,76 15,68 11,68 11,64 9,62 1,62
NetC177_1 on Layer 2 "LAYER_2_NETC177_1_P214" (solid, remove dead copper, pour order 214): 259,131 264,136 264,143 264,149 268,153 285,153 289,157 289,211 299,221 299,227 295,231 293,231 290,234 290,278 308,278 308,156 304,156 297,149 297,145 261,109 217,109 217,122 237,122 246,131
NetC173_2 on Layer 2 "LAYER_2_NETC173_2_P227" (solid, remove dead copper, pour order 227): 348,150 348,0 360,0 360,150
I_HALL_P on Layer 2 "LAYER_2_I_HALL_P_P223" (solid, remove dead copper, pour order 223): 302,67 305,70 305,79 301,83 293,83 286,76 277,76 277,92 301,116 301,148 303,150 314,150 316,148 316,0 302,0
NetC177_2 on Layer 2 "LAYER_2_NETC177_2_P219" (solid, remove dead copper, pour order 219): 340,277 351,277 351,252 357,246 357,221 356,221 348,213 348,205 360,193 360,179 349,168 349,158 340,158
GND on Bottom Layer "BOTTOM_LAYER_GND_P278" (solid, remove dead copper, pour order 278): 1,11 8,11 11,8 11,1 297,1 297,66 272,66 261,55 234,55 223,44 174.13,44 148.13,70 119,70 93,44 1,44
DC_BUS_DAB on Bottom Layer "BOTTOM_LAYER_DC_BUS_DAB_P306" (solid, remove dead copper, pour order 306): 204,76 204,85 209,90 209,103 203,109 203,114 210,114 216,108 216,83 209,76
DC_BUS_NEG on Bottom Layer "BOTTOM_LAYER_DC_BUS_NEG_P305" (solid, remove dead copper, pour order 305): 58,76 57,75 52,75 46,81 46,107 53,114 58,114 58,103 54,99 54,85 58,81
NetH16_1 on Bottom Layer "BOTTOM_LAYER_NETH16_1_P260" (solid, remove dead copper, pour order 260): 245,95 254,95 256,97 256,96.995 320.046,96.995 323.046,93.995 327.046,93.995 327.056,106.995 323.046,106.995 320.046,103.995 245,103.995
I_SW_NEG on Bottom Layer "BOTTOM_LAYER_I_SW_NEG_P283" (solid, remove dead copper, pour order 283): 242,63 260,63 263,66 263,72 247,72 242,67
GND_ISO_AC_SENS on Bottom Layer "BOTTOM_LAYER_GND_ISO_AC_SENS_P282" (solid, remove dead copper, pour order 282): 11,53 35,53 35,59 38,59 38,63 13,63 11,61
I_HALL_N on Bottom Layer "BOTTOM_LAYER_I_HALL_N_P272" (solid, remove dead copper, pour order 272): 258,87 276,87 276,76 258,76
5V_ISO_AC_SENS on Bottom Layer "BOTTOM_LAYER_5V_ISO_AC_SENS_P269" (solid, remove dead copper, pour order 269): 35.5,53 35.5,55 36.2,55.7 36.2,59 38,59 38,53
GND on Bottom Layer "BOTTOM_LAYER_GND_P258" (solid, remove dead copper, pour order 258): 323,43 320,46 288.996,46 288.996,53 320,53 323,56 327.011,56 327,43
GND on Bottom Layer "BOTTOM_LAYER_GND_P192" (solid, remove dead copper, pour order 192): 85,2 85,12 88,12 88,2
12V_IN on Bottom Layer "BOTTOM_LAYER_12V_IN_P193" (solid, remove dead copper, pour order 193): 97,1.984 97,12 100.013,12 100.013,1.984
DC_BUS_POS on Bottom Layer "Layer 1-DC_BUS_POS" (solid, remove dead copper, pour order 204): 159,71 150,80 150,122 168,140 168,185 115,185 115,156 120,151 120,142 114,136 114,70 94,50 66,50 66,78 77,78 88,89 88,104 81,111 65,111 55,121 55.05,121.05 44.1,132 4,132 4,145 13,145 15,147 15,170.019 2,182.988 2,278 132,278 132,267 153,267 153,278 284,278 284,172 243,172 243,145 230,132 219,132 216,129 216,127 205,127 195,117 195,111 185,111 173,99 173,89 184,78 195,78 195,50 176,50 159,67
VAC_POS on Bottom Layer "BOTTOM_LAYER_VAC_POS_P244" (solid, remove dead copper, pour order 244): 1,105 6,105 6,110 36,110 37,111 43,111 46,114 46,120 42,124 1,124
NetD13_1 on Bottom Layer "BOTTOM_LAYER_NETD13_1_P240" (solid, remove dead copper, pour order 240): 21,74 21,68 24,68 24,65 25,64 40,64 45,69 45,75 38,75 38,70 27,70 25,72 23,74
GND_ISO_AC_SENS on Bottom Layer "BOTTOM_LAYER_GND_ISO_AC_SENS_P235" (solid, remove dead copper, pour order 235): 1,83 7,83 7,78 11,78 15,74 15,68 11,68 11,64 9,62 1,62
NetD16_1 on Bottom Layer "BOTTOM_LAYER_NETD16_1_P230" (solid, remove dead copper, pour order 230): 243,82 243,87 252,87 252,73 245,73 239,67 216,67 216,76 237,76
NetC177_1 on Bottom Layer "BOTTOM_LAYER_NETC177_1_P215" (solid, remove dead copper, pour order 215): 245,130 256,130 265,139 265,150 269,154 284,154 290,160 290,212 299,221 299,225 290,234 290,278 308,278 308,156 304,156 296,148 296,144 261,109 217,109 217,122 237,122
NetC173_2 on Bottom Layer "BOTTOM_LAYER_NETC173_2_P224" (solid, remove dead copper, pour order 224): 348,150 348,0 360,0 360,150
NetC177_2 on Bottom Layer "BOTTOM_LAYER_NETC177_2_P218" (solid, remove dead copper, pour order 218): 340,277 351,277 351,252 357,246 357,221 356,221 348,213 348,205 360,193 360,179 349,168 349,158 340,158
NetC4_1 on Bottom Layer "BOTTOM_LAYER_NETC4_1_P198" (solid, remove dead copper, pour order 198): 128,232 133,237 152,237 161,228 185,228 185,215 155,215 154,216 154,226 149,231 134,231 133,230 133,218 129,214 119,214 110,214 101,214 101,226 122,226
GND_ISO_AC_SENS on Top Layer "TOP_LAYER_GND_ISO_AC_SENS_P267" (solid, remove dead copper, pour order 267): 22,61 24,63 34,63 35.2,61.8 35.2,53 11,53 11,61
GND on Top Layer "TOP_LAYER_GND_P280" (solid, remove dead copper, pour order 280): 1,12 6,12 11,7 11,1 297,1 297,66 272,66 261,55 257,51 257,31 240,31 239,32 239,44 175,44 150.188,68.812 136,68.812 136,45 121.771,45 121.771,68.812 118.188,68.812 118,69 93,44 16,44 16,27 1,27
NetC4_1 on Top Layer "TOP_LAYER_NETC4_1_P313" (solid, remove dead copper, pour order 313): 327.7,202.5 327.7,52.5 339.7,52.5 339.7,202.5
GND on Top Layer "TOP_LAYER_GND_P253" (solid, remove dead copper, pour order 253): 198,153 201,153 201,145 198,145
DC_BUS_POS on Top Layer "TOP_LAYER_DC_BUS_POS_P304" (solid, remove dead copper, pour order 304): 45,278 45,250 130,250 130,278
DC_BUS_POS on Top Layer "TOP_LAYER_DC_BUS_POS_P303" (solid, remove dead copper, pour order 303): 253,131 253,143 252,143 252,146 255,149 256,149 256,131
NetC11_1 on Top Layer "TOP_LAYER_NETC11_1_P302" (solid, remove dead copper, pour order 302): 246,137 246,132 249,132 249,137
NetC23_1 on Top Layer "TOP_LAYER_NETC23_1_P301" (solid, remove dead copper, pour order 301): 246,143 246,138 249,138 249,143
NetC25_1 on Top Layer "TOP_LAYER_NETC25_1_P300" (solid, remove dead copper, pour order 300): 195,128 195,123 198,123 198,128
NetC65_1 on Top Layer "TOP_LAYER_NETC65_1_P299" (solid, remove dead copper, pour order 299): 195,134 195,129 198,129 198,134
NetC163_1 on Top Layer "TOP_LAYER_NETC163_1_P298" (solid, remove dead copper, pour order 298): 195,140 195,135 198,135 198,140
NetC71_1 on Top Layer "TOP_LAYER_NETC71_1_P297" (solid, remove dead copper, pour order 297): 201,59 201,54 204,54 204,59
NetC12_1 on Top Layer "TOP_LAYER_NETC12_1_P296" (solid, remove dead copper, pour order 296): 201,71 201,66 204,66 204,71
NetC13_1 on Top Layer "TOP_LAYER_NETC13_1_P295" (solid, remove dead copper, pour order 295): 201,65 201,60 204,60 204,65
NetC24_1 on Top Layer "TOP_LAYER_NETC24_1_P294" (solid, remove dead copper, pour order 294): 187,59 187,54 190,54 190,59
NetC164_1 on Top Layer "TOP_LAYER_NETC164_1_P293" (solid, remove dead copper, pour order 293): 187,65 187,60 190,60 190,65
DC_BUS_POS on Top Layer "TOP_LAYER_DC_BUS_POS_P247" (solid, remove dead copper, pour order 247): 187,75 195,75 195,71 197,71 197,52 194,52 194,66 192,68 187,68
NetC166_1 on Top Layer "TOP_LAYER_NETC166_1_P292" (solid, remove dead copper, pour order 292): 18,145 18,140 21,140 21,145
NetC2_2 on Top Layer "TOP_LAYER_NETC2_2_P291" (solid, remove dead copper, pour order 291): 18,139 18,134 21,134 21,139
NetC168_2 on Top Layer "TOP_LAYER_NETC168_2_P290" (solid, remove dead copper, pour order 290): 63,128 63,123 66,123 66,128
NetC26_2 on Top Layer "TOP_LAYER_NETC26_2_P289" (solid, remove dead copper, pour order 289): 63,134 63,129 66,129 66,134
NetC14_2 on Top Layer "TOP_LAYER_NETC14_2_P288" (solid, remove dead copper, pour order 288): 63,140 63,135 66,135 66,140
NetC15_1 on Top Layer "TOP_LAYER_NETC15_1_P287" (solid, remove dead copper, pour order 287): 73,60 73,55 76,55 76,60
NetC161_1 on Top Layer "TOP_LAYER_NETC161_1_P286" (solid, remove dead copper, pour order 286): 73,66 73,61 76,61 76,66
NetC1_1 on Top Layer "TOP_LAYER_NETC1_1_P285" (solid, remove dead copper, pour order 285): 58,60 58,55 61,55 61,60
NetC3_1 on Top Layer "TOP_LAYER_NETC3_1_P284" (solid, remove dead copper, pour order 284): 58,66 58,61 61,61 61,66
NetD16_1 on Top Layer "TOP_LAYER_NETD16_1_P231" (solid, remove dead copper, pour order 231): 249,75 249,74 248,73 245,73 240,68 240,76 243,79 243,87 252,87 252,75
5V_ISO_AC_SENS on Top Layer "TOP_LAYER_5V_ISO_AC_SENS_P270" (solid, remove dead copper, pour order 270): 31.3,55.3 31.3,57.3 32,58 32,61.3 33.8,61.3 33.8,55.3
5V_ISO_AC_SENS on Top Layer "TOP_LAYER_5V_ISO_AC_SENS_P268" (solid, remove dead copper, pour order 268): 35.5,53 35.5,55 36.2,55.7 36.2,59 38,59 38,53
I_SW_NEG on Top Layer "TOP_LAYER_I_SW_NEG_P265" (solid, remove dead copper, pour order 265): 242,67.001 244.998,70 245.629,70 245.629,64.044 242,64.044
5V_ISO_SN_SENS on Top Layer "TOP_LAYER_5V_ISO_SN_SENS_P266" (solid, remove dead copper, pour order 266): 245.745,64.046 248.762,64.046 248.749,64.058 248.749,70.044 245.75,70.044
NetH13_1 on Top Layer "TOP_LAYER_NETH13_1_P256" (solid, remove dead copper, pour order 256): 4,33 4,39 7,42 11,42 14,39 14,33 12,31 6,31
DC_BUS_DAB on Top Layer "TOP_LAYER_DC_BUS_DAB_P263" (solid, remove dead copper, pour order 263): 138,144 140.88,144 140.88,150 138,150
5V_ISO_DC_SENS on Top Layer "TOP_LAYER_5V_ISO_DC_SENS_P264" (solid, remove dead copper, pour order 264): 140.996,144.001 144.013,144.001 144,144.014 144,150 141.001,150
12V_IN on Top Layer "TOP_LAYER_12V_IN_P262" (solid, remove dead copper, pour order 262): 73.967,16 73.967,15.683 73.96,15.677 76.354,15.677 76.354,15.67 78.024,14 82,14 82,16
12V_IN on Top Layer "TOP_LAYER_12V_IN_P261" (solid, remove dead copper, pour order 261): 97,6.494 100,6.494 100,9 97,9
3V3 on Top Layer "TOP_LAYER_3V3_P191" (solid, remove dead copper, pour order 191): 45.193,28.387 51.136,28.387 51.136,31 46.582,31 45.199,29.617
NetH16_1 on Top Layer "TOP_LAYER_NETH16_1_P259" (solid, remove dead copper, pour order 259): 327,94 323,94 323,107 327.011,107
GND on Top Layer "TOP_LAYER_GND_P257" (solid, remove dead copper, pour order 257): 327,43 323,43 323,56 327.011,56
NetH14_1 on Top Layer "TOP_LAYER_NETH14_1_P255" (solid, remove dead copper, pour order 255): 134,49 124,49 124,58 125,59 133,59 134,58
NetH15_1 on Top Layer "TOP_LAYER_NETH15_1_P254" (solid, remove dead copper, pour order 254): 243,40 243,34 245.002,31.998 251.998,31.998 254,34 254,40 252,42 245,42
12V_FET_DRAIN on Top Layer "TOP_LAYER_12V_FET_DRAIN_P181" (solid, remove dead copper, pour order 181): 65.359,22.973 64.184,22.973 64.184,18.594 65.359,18.594
GND on Top Layer "TOP_LAYER_GND_P182" (solid, remove dead copper, pour order 182): 65.749,21.502 65.774,21.477 69.014,21.477 69.014,24.209 65.754,24.209
12V_OUT on Top Layer "TOP_LAYER_12V_OUT_P183" (solid, remove dead copper, pour order 183): 73.028,13.71 73.028,14.595 73.623,15.19 74.319,15.19 74.331,15.457 74.321,15.467 72.57,15.467 71.293,16.744 71.293,17.667 61.384,17.667 61.384,13.71
NetC58_2 on Top Layer "TOP_LAYER_NETC58_2_P184" (solid, remove dead copper, pour order 184): 43.922,16.704 43.919,16.706 43.597,16.706 43.597,17.381 43.173,17.805 43.173,22.5 44.63,22.5 44.63,18.188 43.915,17.473
NetC70_1 on Top Layer "TOP_LAYER_NETC70_1_P185" (solid, remove dead copper, pour order 185): 44.109,16.722 44.107,16.725 44.107,17.272 46.517,19.682 60.048,19.682 60.048,16.727 44.389,16.727
5V on Top Layer "TOP_LAYER_5V_P186" (solid, remove dead copper, pour order 186): 41.796,18.55 31.068,18.55 31.068,22.5 41.699,22.5 41.781,22.417
no net on Top Layer "TOP_LAYER_NONET_P187" (solid, remove dead copper, pour order 187): 33.092,17.928 33.073,17.91 33.073,15.982
GND on Top Layer "TOP_LAYER_GND_P188" (solid, remove dead copper, pour order 188): 41.288,14.414 33.018,14.414 33.018,17.904 42.687,17.904 43.463,17.129 43.463,16.517 57.34,16.517 57.34,13.62 46.571,13.62 44.683,15.508 44.669,15.508 44.044,16.132 43.007,16.132
NetC22_1 on Top Layer "TOP_LAYER_NETC22_1_P189" (solid, remove dead copper, pour order 189): 34.056,23.742 34.03,23.768 34.03,27.234 43.502,27.234 43.534,27.201 43.495,27.163 43.495,26.451 41.769,26.451 38.995,23.678
GND on Top Layer "TOP_LAYER_GND_P190" (solid, remove dead copper, pour order 190): 36.218,29.9 40.729,29.9 42.414,28.215 49.273,28.215 49.273,25.066 46.651,24.997 44.111,27.537 36.218,27.537
DC_BUS_DAB on Top Layer "TOP_LAYER_DC_BUS_DAB_P248" (solid, remove dead copper, pour order 248): 183,53 179,53 179,65 183,65
GND on Top Layer "TOP_LAYER_GND_P251" (solid, remove dead copper, pour order 251): 50,145 54,145 54,154 50,154
DC_BUS_POS on Top Layer "TOP_LAYER_DC_BUS_POS_P250" (solid, remove dead copper, pour order 250): 114,148 114,142 120,142 120,156 104,156 104,148
DC_BUS_POS on Top Layer "TOP_LAYER_DC_BUS_POS_P246" (solid, remove dead copper, pour order 246): 187,114 194,114 194,120 191,120 191,141 187,141
DC_BUS_DAB on Top Layer "Top Layer-DC_BUS_DAB" (solid, remove dead copper, pour order 206): 202,103 201,104 201,121 202,122 202,140 211,140 215,144 215,155 210,160 163,160 160,157 160,147 153,147 153,174 164,185 164,208 197,208 197,173 203,167 214,167 218,171 218,208 284,208 284,160 242,160 242,131 236,131 232,127 217,127 211,121 211,113 216,108 216,84 215,83 211,79 210,78 210,53 208,53 208,75 203,75 200,78 200,84 207,91 207,98
VAC_POS on Top Layer "TOP_LAYER_VAC_POS_P245" (solid, remove dead copper, pour order 245): 43,123 24,123 23,124 1,124 1,110 18,110 18,108 20,108 20,120 37,120 37,114 44,114 45,115 45,121
NetD13_1 on Top Layer "TOP_LAYER_NETD13_1_P241" (solid, remove dead copper, pour order 241): 21,74 21,68 24,68 24,65 25,64 40,64 45,69 45,75 38,75 38,70 27,70 25,72 23,74
NetC105_2 on Top Layer "TOP_LAYER_NETC105_2_P237" (solid, remove dead copper, pour order 237): 19,77 19,79 18,79 17,80 14,80 14,77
